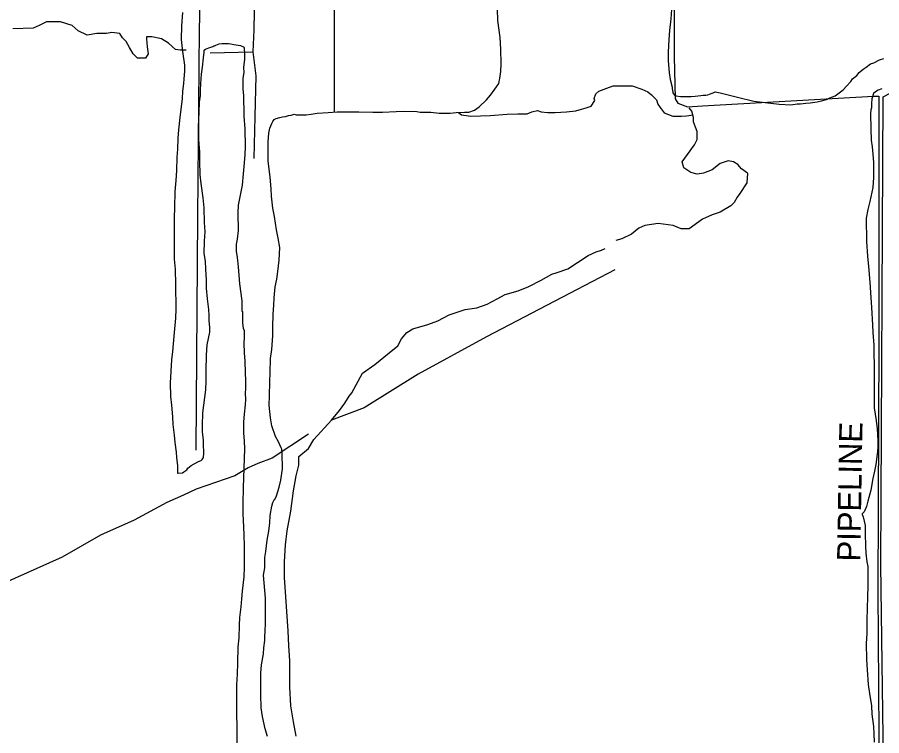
# Model space of a CAD drawing. Extents: x 3297716 to 3335574, y 688621 to 713991.
# Drawn here: x 3302403 to 3305497, y 705686 to 708260 of the extents above; entities that cross this region are included whole.
import ezdxf

# ---------------------------------------------------------------- set-up
doc = ezdxf.new("R2010")
doc.units = 0
for name, color, linetype in [('V-SITE-VEGE', 7, 'Continuous'), ('V-TOPO-SHOR', 7, 'Continuous'), ('V-UTIL-IDEN', 7, 'Continuous'), ('V-UTIL-LINE', 7, 'Continuous')]:
    doc.layers.add(name, color=color, linetype=linetype)

msp = doc.modelspace()

# ---------------------------------------------------------------- linework, layer by layer
at = {"layer": 'V-SITE-VEGE'}
for p, q in [((3302994.5, 708276.5), (3302991.4, 708229.2)), ((3302991.4, 708229.2), (3302989.5, 708180.7)), ((3302989.5, 708180.7), (3302994.1, 708137.8)), ((3303072.2, 708142.6), (3303076.6, 708146)), ((3303072.3, 708134.9), (3303072.2, 708142.6)), ((3303076.6, 708146), (3303088.7, 708150.4)), ((3303088.7, 708150.4), (3303103, 708154.9)), ((3303103, 708154.9), (3303106.3, 708157.1)), ((3303106.3, 708157.1), (3303108.5, 708158.2)), ((3303108.5, 708158.2), (3303114, 708160.5)), ((3303114, 708160.5), (3303126, 708164.9)), ((3303126, 708164.9), (3303137, 708166.1)), ((3303137, 708166.1), (3303159.1, 708166.2)), ((3303159.1, 708166.2), (3303167.9, 708165.1)), ((3303167.9, 708165.1), (3303177.8, 708163)), ((3303177.8, 708163), (3303202, 708158.7)), ((3303202, 708158.7), (3303213.1, 708154.4)), ((3303213.1, 708154.4), (3303215.3, 708151.1)), ((3303215.3, 708151.1), (3303215.3, 708147.8)), ((3303215.3, 708147.8), (3303216.5, 708129.1)), ((3302994.1, 708137.8), (3303002, 708088.3)), ((3303065.9, 708081), (3303069.1, 708115.1)), ((3303069.1, 708115.1), (3303072.3, 708134.9)), ((3303216.6, 708110.3), (3303213.4, 708079.5)), ((3303216.5, 708129.1), (3303216.6, 708110.3)), ((3303002, 708088.3), (3303002.1, 708067.4)), ((3303062.7, 708056.7), (3303065.9, 708081)), ((3303213.4, 708079.5), (3303213.5, 708063)), ((3303002.1, 708067.4), (3302999, 708039.9)), ((3303059.6, 708022.6), (3303062.7, 708056.7)), ((3303213.5, 708063), (3303210.3, 708041)), ((3302998, 708022.3), (3302994.8, 707994.7)), ((3302999, 708039.9), (3302998, 708022.3)), ((3303058.6, 708000.6), (3303059.6, 708022.6)), ((3303210.3, 708041), (3303210.5, 708003.5)), ((3302994.8, 707994.7), (3302992.7, 707969.4)), ((3303058.7, 707979.7), (3303058.6, 708000.6)), ((3303210.5, 708003.5), (3303212.8, 707978.2)), ((3302992.7, 707969.4), (3302985.4, 707901.1)), ((3303054.6, 707920.2), (3303055.5, 707955.4)), ((3303055.5, 707955.4), (3303058.7, 707979.7)), ((3303212.8, 707978.2), (3303212.9, 707959.5)), ((3303212.9, 707959.5), (3303214.2, 707929.8)), ((3303214.2, 707929.8), (3303214.3, 707905.6)), ((3302985.4, 707901.1), (3302980.1, 707857.1)), ((3303052.6, 707893.8), (3303054.6, 707920.2)), ((3303052.9, 707822.2), (3303052.6, 707893.8)), ((3303214.3, 707905.6), (3303217.8, 707860.5)), ((3303217.8, 707860.5), (3303218.2, 707796.6)), ((3302980.1, 707857.1), (3302978, 707827.3)), ((3302978, 707827.3), (3302977.1, 707787.7)), ((3303056.4, 707777.1), (3303052.9, 707822.2)), ((3302977.1, 707787.7), (3302974, 707759.1)), ((3303056.6, 707744.1), (3303056.4, 707777.1)), ((3303217.2, 707766.9), (3303214.1, 707725.1)), ((3303218.2, 707796.6), (3303217.2, 707766.9)), ((3302974, 707759.1), (3302973.1, 707710.6)), ((3303058, 707695.6), (3303056.6, 707744.1)), ((3302973.1, 707710.6), (3302970, 707675.4)), ((3303214.1, 707725.1), (3303212, 707699.7)), ((3302970, 707675.4), (3302966.9, 707635.7)), ((3303061.4, 707664.8), (3303058, 707695.6)), ((3303212, 707699.7), (3303207.9, 707659)), ((3303068.3, 707613.1), (3303061.4, 707664.8)), ((3303207.9, 707659), (3303193.9, 707587.4)), ((3302966.9, 707635.7), (3302966.1, 707578.5)), ((3303071.8, 707577.9), (3303068.3, 707613.1)), ((3303193.9, 707587.4), (3303192.9, 707559.8)), ((3302966.1, 707578.5), (3302964.1, 707541.1)), ((3303073.1, 707525.1), (3303071.8, 707577.9)), ((3303192.9, 707559.8), (3303193.3, 707496)), ((3302964.1, 707541.1), (3302964.8, 707393.6)), ((3303075.5, 707491), (3303073.1, 707525.1)), ((3303073.5, 707458), (3303075.5, 707491)), ((3303193.3, 707496), (3303190.1, 707465.1)), ((3303072.6, 707413.9), (3303073.5, 707458)), ((3303190.1, 707465.1), (3303186.9, 707447.5)), ((3303186.9, 707447.5), (3303187, 707422.2)), ((3303077.1, 707386.4), (3303072.6, 707413.9)), ((3303187, 707422.2), (3303190.4, 707399.1)), ((3303190.4, 707399.1), (3303193.9, 707366.1)), ((3302964.8, 707393.6), (3302968.3, 707357.3)), ((3303078.4, 707357.8), (3303077.1, 707386.4)), ((3303193.9, 707366.1), (3303198.6, 707305.6)), ((3302968.3, 707357.3), (3302969.7, 707303.3)), ((3303080.8, 707318.2), (3303078.4, 707357.8)), ((3302969.7, 707303.3), (3302970.1, 707214.2)), ((3303080.9, 707289.6), (3303080.8, 707318.2)), ((3303198.6, 707305.6), (3303206.6, 707244)), ((3303084.4, 707251.1), (3303080.9, 707289.6)), ((3303089, 707213.7), (3303084.4, 707251.1)), ((3303206.6, 707244), (3303206.8, 707207.6)), ((3302970.1, 707214.2), (3302969.2, 707182.2)), ((3303090.2, 707191.6), (3303089, 707213.7)), ((3302969.2, 707182.2), (3302965, 707130.5)), ((3303090.3, 707172.9), (3303090.2, 707191.6)), ((3303206.8, 707207.6), (3303209, 707206.6)), ((3303209, 707206.6), (3303209.2, 707164.7)), ((3303092.6, 707149.8), (3303090.3, 707172.9)), ((3303092.7, 707132.2), (3303092.6, 707149.8)), ((3303209.2, 707164.7), (3303211.5, 707146)), ((3302965, 707130.5), (3302958.8, 707063.3)), ((3303083, 707087), (3303092.7, 707132.2)), ((3303211.5, 707146), (3303214.9, 707138.3)), ((3303214.9, 707138.3), (3303215, 707111.9)), ((3303079.9, 707049.6), (3303083, 707087)), ((3303215, 707111.9), (3303214, 707094.3)), ((3303214, 707094.3), (3303215.3, 707056.9)), ((3302958.8, 707063.3), (3302955.6, 707032.5)), ((3303215.3, 707056.9), (3303217.6, 707029.4)), ((3302955.6, 707032.5), (3302950.5, 706951)), ((3303079.1, 706993.5), (3303079.9, 707049.6)), ((3303217.6, 707029.4), (3303219, 706985.3)), ((3303079.3, 706958.2), (3303079.1, 706993.5)), ((3303219, 706985.3), (3303220.2, 706960)), ((3302950.5, 706951), (3302951.9, 706901.4)), ((3303078.4, 706925.2), (3303079.3, 706958.2)), ((3303220.2, 706960), (3303220.3, 706930.3)), ((3302951.9, 706901.4), (3302955.3, 706870.6)), ((3303067.8, 706842.6), (3303078.4, 706925.2)), ((3303220.3, 706930.3), (3303219.3, 706913.8)), ((3303219.3, 706913.8), (3303219.4, 706890.7)), ((3302955.3, 706870.6), (3302958.9, 706828.8)), ((3303218.4, 706872), (3303215.3, 706837.8)), ((3303219.4, 706890.7), (3303218.4, 706872)), ((3303065.8, 706797.4), (3303067.8, 706842.6)), ((3302958.9, 706828.8), (3302960.1, 706801.3)), ((3303215.3, 706837.8), (3303213.2, 706811.4)), ((3303213.2, 706811.4), (3303213.4, 706771.8)), ((3302960.1, 706801.3), (3302964.7, 706762.8)), ((3303065.9, 706773.2), (3303065.8, 706797.4)), ((3302964.7, 706762.8), (3302967, 706736.4)), ((3303069.4, 706746.8), (3303065.9, 706773.2)), ((3303069.5, 706721.5), (3303069.4, 706746.8)), ((3303213.4, 706771.8), (3303215.8, 706742.1)), ((3302967, 706736.4), (3302971.6, 706702.3)), ((3303070.6, 706709.4), (3303069.5, 706721.5)), ((3303215.8, 706742.1), (3303215.9, 706714.5)), ((3302971.6, 706702.3), (3302972.8, 706682.5)), ((3303069.7, 706683), (3303070.7, 706698.4)), ((3303070.7, 706698.4), (3303070.6, 706709.4)), ((3303215.9, 706714.5), (3303212.2, 706575.8)), ((3302972.8, 706682.5), (3302976.3, 706652.8)), ((3303013.7, 706645.3), (3303025.8, 706654.1)), ((3303025.8, 706654.1), (3303035.7, 706660.8)), ((3303035.7, 706660.8), (3303052.1, 706668.6)), ((3303052.1, 706668.6), (3303060.9, 706671.9)), ((3303060.9, 706671.9), (3303065.3, 706675.3)), ((3303065.3, 706675.3), (3303069.7, 706683)), ((3302976.3, 706652.8), (3302976.4, 706626.4)), ((3302976.4, 706626.4), (3302978.6, 706626.4)), ((3302978.6, 706626.4), (3302994, 706628.7)), ((3302994, 706628.7), (3302999.5, 706632)), ((3302999.5, 706632), (3303009.4, 706638.6)), ((3303009.4, 706638.6), (3303013.7, 706645.3)), ((3303212.2, 706575.8), (3303210.3, 706518.6)), ((3303210.3, 706518.6), (3303210.5, 706482.2)), ((3303210.5, 706482.2), (3303212.9, 706433.8)), ((3303212.9, 706433.8), (3303214.2, 706406.3)), ((3303214.2, 706406.3), (3303215.5, 706365.6)), ((3303215.5, 706365.6), (3303215.6, 706338.1)), ((3303215.6, 706338.1), (3303214.8, 706289.6)), ((3303214.8, 706289.6), (3303213.8, 706255.5)), ((3303213.8, 706255.5), (3303207.5, 706204.8)), ((3303207.5, 706204.8), (3303205.4, 706177.3)), ((3303205.4, 706177.3), (3303203.4, 706147.6)), ((3303203.4, 706147.6), (3303198.1, 706110.1)), ((3303198.1, 706110.1), (3303197.1, 706082.6)), ((3303197.1, 706082.6), (3303196.2, 706037.5)), ((3303196.2, 706037.5), (3303193.1, 706003.3)), ((3303193.1, 706003.3), (3303191.2, 705947.2)), ((3303191.2, 705947.2), (3303190.3, 705907.5)), ((3303190.3, 705907.5), (3303188.3, 705869)), ((3303188.3, 705869), (3303190.2, 705474.9))]:
    msp.add_line(p, q, dxfattribs=at)
for points in [[(3303321.5, 707228.8), (3303322.5, 707255.2), (3303326.7, 707294.9), (3303332, 707322.4), (3303336.3, 707348.8), (3303340.5, 707389.6), (3303342.5, 707435.8), (3303336.8, 707468.8), (3303331.1, 707498.5), (3303323.2, 707546.9), (3303317.5, 707576.6), (3303312.9, 707619.5), (3303311.7, 707645.9), (3303308.2, 707687.7), (3303301.3, 707746.1), (3303300.9, 707814.3), (3303303, 707845.1), (3303307.3, 707862.8), (3303313.8, 707879.3), (3303318.2, 707887), (3303322.5, 707893.7), (3303330.2, 707897), (3303342.3, 707901.5), (3303352.2, 707903.7), (3303363.2, 707904.9), (3303374.2, 707908.2), (3303383, 707909.4), (3303394, 707912.7), (3303401.7, 707910.6), (3303436.9, 707910.8), (3303454.5, 707913), (3303476.5, 707916.5), (3303516.1, 707918.9), (3303548.1, 707921.2), (3303625.1, 707921.6), (3303675.8, 707919.7), (3303709.9, 707919.8), (3303759.4, 707922.3), (3303789.1, 707923.5), (3303833.2, 707922.7), (3303845.3, 707920.5), (3303883.8, 707919.6), (3303913.5, 707916.5), (3303952.1, 707916.7), (3303974.1, 707919), (3304003.8, 707920.2), (3304019.2, 707920.3), (3304040.1, 707927), (3304056.5, 707939.2), (3304082.8, 707964.6), (3304097, 707981.2), (3304112.3, 708002.2), (3304118.9, 708011.1), (3304126.6, 708023.2), (3304127.6, 708028.7), (3304129.8, 708036.4), (3304130.9, 708040.8), (3304134, 708066.2), (3304135, 708092.6), (3304133.6, 708145.4), (3304131.2, 708187.3), (3304123.2, 708248.9), (3304121.9, 708288.5)], [(3304745, 708287.2), (3304742.9, 708254.2), (3304737.6, 708212.3), (3304735.6, 708180.4), (3304732.5, 708135.2), (3304732.7, 708105.5), (3304736.2, 708060.4), (3304740.7, 708037.3), (3304747.5, 708009.8), (3304747.5, 708003.2), (3304749.8, 707992.2), (3304749.8, 707988.9), (3304755.3, 707981.2), (3304761.9, 707979.1), (3304777.4, 707975.9), (3304814.8, 707976), (3304830.2, 707977.2), (3304850, 707979.5), (3304858.8, 707980.7), (3304867.6, 707980.7), (3304875.3, 707981.9)], [(3304875.3, 707981.9), (3304887.4, 707987.4), (3304894, 707989.7), (3304901.7, 707993), (3304919.3, 707989.8), (3304981, 707973.6), (3305039.4, 707959.6), (3305130.8, 707949), (3305171.6, 707945.9), (3305194.7, 707949.3), (3305206.8, 707949.4), (3305225.5, 707951.7), (3305240.9, 707952.9), (3305266.2, 707957.4), (3305281.6, 707960.8), (3305300.3, 707965.3), (3305311.3, 707970.8), (3305331, 707978.7), (3305345.3, 707989.7), (3305359.6, 707999.7), (3305371.6, 708013), (3305386.9, 708029.6), (3305393.5, 708039.5), (3305408.8, 708051.7), (3305416.5, 708061.6), (3305430.7, 708073.8), (3305441.7, 708081.6), (3305457.1, 708092.7), (3305469.1, 708097.1), (3305490, 708107.1), (3305505.4, 708112.7)], [(3305498.2, 708003.7), (3305485, 707999.2), (3305475.2, 707992.6), (3305468.6, 707987.1), (3305462.1, 707968.3), (3305461.1, 707950.7), (3305461.1, 707935.3), (3305459, 707928.7), (3305457.9, 707915.4), (3305458.2, 707859.3), (3305459.5, 707819.7), (3305463, 707795.5), (3305465.3, 707769.1), (3305467.6, 707739.4), (3305467.9, 707686.5), (3305465.9, 707650.2), (3305455.1, 707600.6), (3305447.6, 707570.8), (3305442.2, 707540), (3305442.6, 707456.3), (3305446.2, 707404.6), (3305449.7, 707367.2), (3305454.4, 707311.1), (3305457.9, 707273.7), (3305460.4, 707220.9), (3305465.1, 707158.1), (3305466.3, 707130.6), (3305468.7, 707085.5), (3305468.9, 707055.8), (3305470.2, 707014), (3305471, 706861), (3305477.8, 706815.9), (3305481.3, 706786.2), (3305483.7, 706744.3), (3305483.8, 706717.9), (3305481.7, 706694.8), (3305476.4, 706658.4), (3305472.1, 706634.2), (3305465.6, 706607.8), (3305458.1, 706565.9), (3305447.3, 706526.2), (3305443, 706507.5), (3305434.3, 706488.7), (3305427.8, 706481), (3305427.8, 706478.8), (3305431.1, 706470), (3305437.9, 706439.2), (3305438, 706410.6)], [(3303298.5, 705683.2), (3303290.6, 705710.6), (3303280.5, 705755.7), (3303275.9, 705786.5), (3303274.6, 705833.9), (3303274.4, 705865.8), (3303275.3, 705910.9), (3303277.3, 705940.6), (3303284.9, 705980.3), (3303285.8, 706001.2), (3303289, 706027.7), (3303289, 706037.6), (3303289.9, 706064), (3303292, 706086), (3303291.6, 706179.6), (3303284.5, 706262.1), (3303288.8, 706287.4), (3303288.7, 706300.7), (3303289.7, 706324.9), (3303292.9, 706345.8), (3303297.1, 706386.6), (3303303.5, 706419.6), (3303306.7, 706449.4), (3303307.7, 706475.8), (3303314.1, 706508.8), (3303318.4, 706522.1), (3303322.8, 706532), (3303325, 706533.1), (3303330.4, 706545.2), (3303340.2, 706577.2), (3303346.7, 706601.5), (3303352, 706642.2), (3303351.7, 706698.4), (3303350.5, 706712.7), (3303347.2, 706718.2), (3303338.3, 706739), (3303327.2, 706758.8), (3303313.8, 706796.1), (3303309.2, 706824.7), (3303304.6, 706870.9), (3303305.5, 706904), (3303307.5, 706954.6), (3303308.4, 706987.6), (3303309.2, 707037.2), (3303314.6, 707070.2), (3303317.6, 707118.7), (3303317.5, 707149.5), (3303319.4, 707196.9), (3303321.5, 707228.8)], [(3305438, 706410.6), (3305439.3, 706365.4), (3305440.6, 706340.1), (3305444, 706309.3), (3305447.4, 706292.8), (3305447.8, 706219.1), (3305446.8, 706188.3), (3305444.9, 706138.7), (3305444, 706105.7), (3305444.2, 706052.8), (3305442.2, 706016.5), (3305442.5, 705959.3), (3305446, 705923), (3305449.6, 705870.1), (3305454.1, 705838.2), (3305460.9, 705793.1), (3305462.2, 705763.4), (3305467.9, 705719.4), (3305469.2, 705693), (3305470.4, 705663.3)]]:
    msp.add_lwpolyline(points, dxfattribs=at)
at = {"layer": 'V-TOPO-SHOR'}
msp.add_line((3303093.5, 708132.4), (3303245.7, 708135.6), dxfattribs=at)
for points in [[(3303232.2, 709578.3), (3303261.7, 709560.6), (3303263.2, 709158.3), (3303255.8, 708838.5), (3303257.3, 708692.6), (3303255.8, 708543.7), (3303249.9, 708215.1), (3303245.7, 708135.6), (3303257.3, 708050), (3303252.8, 707904.1), (3303249.9, 707753.8)], [(3303538.8, 707918.9), (3303538.8, 708297.6), (3303541.7, 708735.3), (3303544.6, 709214.3), (3303547.6, 709339.6), (3303557.9, 709373.5), (3303569.7, 709400), (3303585.9, 709425), (3303593.3, 709441.2), (3303593.3, 709454.5), (3303593.3, 709464.8), (3303593.3, 709469.3)], [(3304754.4, 709146.7), (3304754.4, 708119.7), (3304757.6, 707967.6), (3304767.1, 707951.7), (3304802, 707939), (3304855.8, 707942.2), (3305467.6, 707977.1), (3305486.6, 707977.1), (3305486.6, 707102.3), (3305483.4, 706205.2), (3305489.8, 705346.3)], [(3303042.8, 706709.2), (3303049.1, 707546), (3303055.5, 708214.8), (3303061.8, 708458.9)], [(3303007.9, 708141.9), (3302985.7, 708141.9), (3302969.9, 708145.1), (3302944.5, 708167.3), (3302919.2, 708183.1), (3302884.3, 708189.4), (3302865.3, 708189.4), (3302865.3, 708183.1), (3302868.5, 708154.6), (3302871.6, 708129.2), (3302862.1, 708113.4), (3302833.6, 708113.4), (3302817.8, 708129.2), (3302805.1, 708151.4), (3302792.4, 708173.6), (3302779.7, 708186.3), (3302770.2, 708202.1), (3302741.7, 708205.3), (3302722.7, 708202.1), (3302687.8, 708202.1), (3302652.9, 708195.8), (3302621.2, 708211.6), (3302599, 708230.7), (3302557.8, 708243.3), (3302507.1, 708243.3), (3302481.8, 708230.7), (3302459.6, 708221.1), (3302386.7, 708218)], [(3303982.3, 707918.9), (3303992.7, 707910), (3304026.6, 707905.6), (3304095.8, 707908.5), (3304156.3, 707913), (3304194.6, 707914.4), (3304228.5, 707914.4), (3304244.7, 707921.8), (3304265.3, 707926.2), (3304278.6, 707921.8), (3304300.7, 707918.9), (3304328.7, 707918.9), (3304368.5, 707921.8), (3304402.4, 707924.8), (3304423, 707930.7), (3304439.2, 707935.1), (3304456.9, 707941), (3304470.2, 707961.6), (3304468.7, 707969), (3304474.6, 707985.2), (3304484.9, 707995.5), (3304512.9, 708005.8), (3304536.5, 708014.7), (3304554.2, 708014.7), (3304577.7, 708014.7), (3304604.3, 708014.7), (3304638.2, 708002.9), (3304660.3, 707992.6), (3304673.5, 707982.2), (3304691.2, 707964.6), (3304695.6, 707948.3), (3304704.5, 707936.6), (3304719.2, 707917.4), (3304750.2, 707905.6), (3304781.1, 707905.6), (3304798.8, 707907.1), (3304822.4, 707910)], [(3305017.5, 707701.3), (3304995.3, 707717.2), (3304982.6, 707733), (3304966.8, 707742.5), (3304947.8, 707745.7), (3304919.2, 707736.2), (3304890.7, 707714), (3304859, 707701.3), (3304836.8, 707698.2), (3304814.6, 707704.5), (3304789.3, 707720.3), (3304782.9, 707742.5), (3304802, 707767.9), (3304827.3, 707802.8), (3304836.8, 707821.8), (3304836.8, 707834.4), (3304836.8, 707850.3), (3304830.5, 707866.1), (3304824.1, 707885.2), (3304824.1, 707901), (3304817.8, 707923.2), (3304808.3, 707935.9)], [(3305017.5, 707701.3), (3305014.3, 707666.5), (3304989, 707628.4), (3304979.5, 707615.7), (3304969.9, 707596.7), (3304957.3, 707584), (3304919.2, 707561.9), (3304890.7, 707552.3), (3304855.8, 707536.5), (3304808.3, 707501.6), (3304779.8, 707501.6), (3304751.2, 707514.3), (3304697.4, 707520.7), (3304649.8, 707514.3), (3304627.6, 707504.8), (3304602.3, 707482.6), (3304567.4, 707466.8), (3304545.2, 707460.4)], [(3303401, 705685.4), (3303391.5, 705736.1), (3303382, 705793.2), (3303378.8, 705859.8), (3303378.8, 705901), (3303378.8, 705954.8), (3303375.6, 706008.7), (3303372.4, 706062.6), (3303359.8, 706252.8), (3303359.8, 706309.8), (3303362.9, 706370.1), (3303369.3, 706420.8), (3303382, 706490.5), (3303391.5, 706563.4), (3303401, 706617.3), (3303410.5, 706655.3), (3303410.5, 706687), (3303445.3, 706715.6), (3303464.4, 706747.3), (3303527.8, 706817), (3303556.3, 706851.9), (3303575.3, 706877.2), (3303591.1, 706902.6), (3303600.7, 706915.2), (3303638.7, 706985), (3303683.1, 707016.7), (3303733.8, 707057.9), (3303765.5, 707083.2), (3303778.2, 707108.6), (3303797.2, 707130.8), (3303819.4, 707143.5), (3303873.2, 707159.3), (3303908.1, 707172), (3303949.3, 707194.2), (3304006.4, 707213.2), (3304047.6, 707219.5), (3304085.6, 707232.2), (3304120.5, 707251.2), (3304149, 707267.1), (3304196.6, 707279.8), (3304234.6, 707295.6), (3304279, 707317.8), (3304317, 707340), (3304336, 707346.3), (3304374.1, 707359), (3304408.9, 707381.2), (3304447, 707406.5), (3304475.5, 707419.2), (3304494.5, 707425.6), (3304507.2, 707431.9)], [(3304542, 707355.8), (3304082.4, 707114.9), (3303838.4, 706981.8), (3303645, 706861.4), (3303527.8, 706817)], [(3303445.3, 706766.3), (3303315.4, 706680.7), (3303264.7, 706661.7), (3303229.8, 706645.8), (3303182.3, 706617.3), (3303042.8, 706569.8), (3302998.4, 706547.6), (3302938.2, 706522.2), (3302820.9, 706458.8), (3302700.5, 706404.9), (3302564.2, 706325.7), (3302393, 706249.6), (3302215.5, 706170.4), (3302003.2, 706056.3), (3301838.3, 705973.9)]]:
    msp.add_lwpolyline(points, dxfattribs=at)
at = {"layer": 'V-UTIL-LINE'}
msp.add_lwpolyline([(3303448.6, 701140.2), (3303930.9, 701797.4), (3304511.5, 702619.9), (3304648.8, 702913.1), (3304845.7, 703471.7), (3305528, 703789.5), (3305487.4, 703865.8), (3305258.5, 704537), (3305508.3, 705244), (3305494.5, 706298), (3305502.5, 707975.1), (3306265.9, 708377.2)], dxfattribs=at)

# ---------------------------------------------------------------- texts
at = {"layer": 'V-UTIL-IDEN'}
msp.add_text('PIPELINE', height=83, rotation=89.029, dxfattribs=at).set_placement((3305420.5, 706309.9))

doc.saveas('drawing.dxf')
